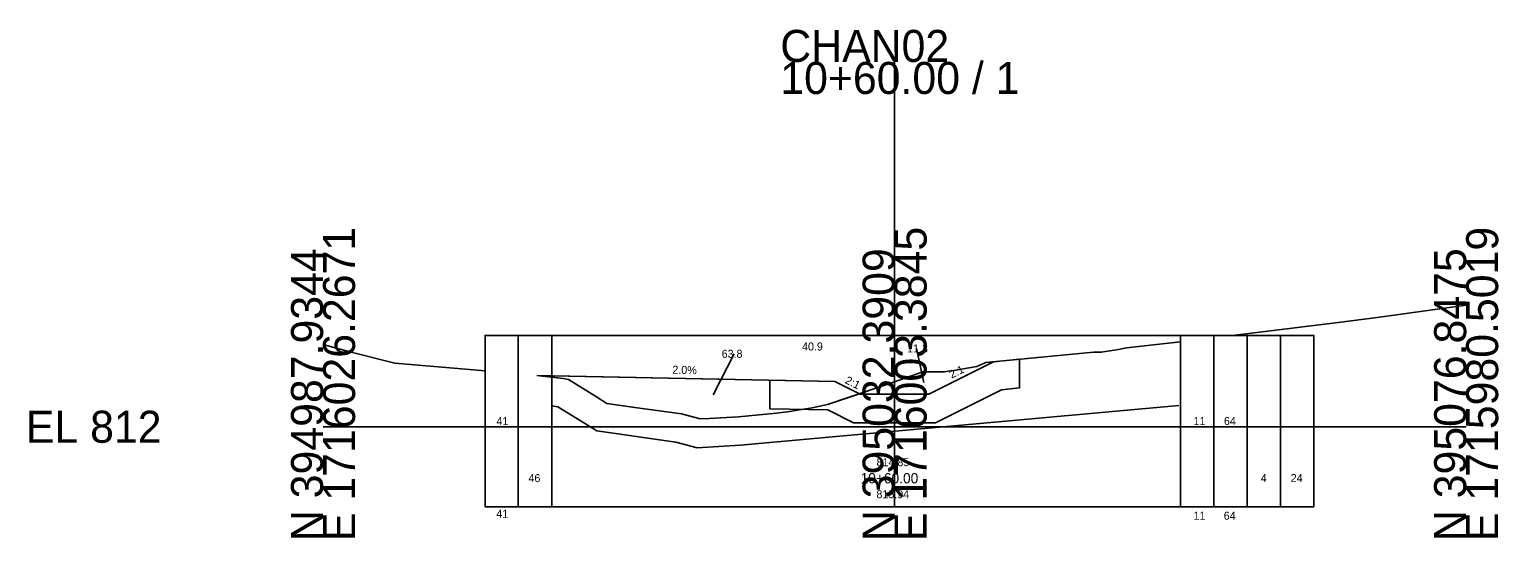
# Model space of a CAD drawing. Extents: x -26 to 103, y -10 to 16052.
# Drawn here: x -25.7 to 102.8, y 9490.3 to 9534.7 of the extents above; entities that cross this region are included whole.
import ezdxf

# ---------------------------------------------------------------- set-up
doc = ezdxf.new("R2010")
doc.units = 0
for name, color, linetype in [('GK_Cells', 7, 'Continuous'), ('SC_Scratch17', 7, 'Continuous'), ('SH_Text', 7, 'Continuous'), ('UT_X_Water', 7, 'Continuous'), ('XS_P_Annotation', 7, 'Continuous'), ('XS_P_Boundary', 7, 'Continuous'), ('XS_P_Earthwork_Shapes', 7, 'Continuous'), ('XS_P_Finished_Grade', 7, 'Continuous'), ('XS_X_Ground_Line', 7, 'Continuous')]:
    doc.layers.add(name, color=color, linetype=linetype)

msp = doc.modelspace()

# ---------------------------------------------------------------- linework, layer by layer
at = {"layer": 'GK_Cells'}
for p, q in [((50, 9500), (50, 9531.9)), ((0, 9500), (50, 9500)), ((50, 9500), (100, 9500))]:
    msp.add_line(p, q, dxfattribs=at)
at = {"layer": 'SC_Scratch17'}
msp.add_lwpolyline([(39.07, 9504.08), (44.77, 9503.97), (47, 9502.85), (53, 9502.85), (58.66, 9505.68), (60.92, 9505.9), (60.92, 9503.39), (59.36, 9503.24), (53.59, 9500.35), (46.41, 9500.35), (44.16, 9501.48), (39.07, 9501.58)], close=True, dxfattribs=at)
at = {"layer": 'UT_X_Water'}
msp.add_lwpolyline([(20, 9501.82), (20.55, 9501.75), (22.59, 9500.5), (23.94, 9499.63), (30.86, 9498.66), (32.73, 9498.16), (36.52, 9498.39), (74.85, 9501.87)], dxfattribs=at)
at = {"layer": 'XS_P_Boundary'}
for p, q in [((17.08, 9493.01), (17.08, 9507.99)), ((20, 9493.01), (20, 9507.99)), ((50, 9493.01), (50, 9507.99)), ((75, 9493.01), (75, 9507.99)), ((77.92, 9493.01), (77.92, 9507.99)), ((80.83, 9493.01), (80.83, 9507.99)), ((83.75, 9493.01), (83.75, 9507.99)), ((15.63, 9500.5), (15.63, 9500.5)), ((76.46, 9500.5), (76.46, 9500.5)), ((79.38, 9500.5), (79.38, 9500.5)), ((18.54, 9495.51), (18.54, 9495.51)), ((82.29, 9495.51), (82.29, 9495.51)), ((85.21, 9495.51), (85.21, 9495.51))]:
    msp.add_line(p, q, dxfattribs=at)
msp.add_lwpolyline([(14.17, 9493.01), (14.17, 9507.99), (86.67, 9507.99), (86.67, 9493.01)], close=True, dxfattribs=at)
at = {"layer": 'XS_P_Earthwork_Shapes'}
for p, q in [((34.12, 9502.79), (35.97, 9506.38)), ((52.56, 9503.88), (51.92, 9506.85)), ((53, 9502.85), (58.66, 9505.68)), ((58.66, 9505.68), (57.98, 9505.61)), ((44.77, 9503.97), (20, 9504.46)), ((20, 9504.46), (20, 9504.34)), ((20, 9504.34), (21.01, 9504.22)), ((46.92, 9502.89), (44.77, 9503.97)), ((47, 9502.85), (53, 9502.85))]:
    msp.add_line(p, q, dxfattribs=at)
for points in [[(18.71, 9504.49), (44.77, 9503.97), (47, 9502.85), (53, 9502.85), (58.66, 9505.68)], [(57.98, 9505.61), (57.18, 9505.26), (55.02, 9504.9), (54.68, 9504.86), (54.36, 9504.81), (52.47, 9504.79), (50, 9503.94), (46.98, 9502.91)], [(21.01, 9504.22), (21.47, 9504.12), (23.92, 9502.62), (24.83, 9502.03), (27.26, 9501.69), (31.37, 9501.12), (32.98, 9500.68), (33.78, 9500.73), (36.33, 9500.88), (39.67, 9501.19), (40.82, 9501.34), (41.49, 9501.45), (42.78, 9501.65), (44.13, 9501.94), (46.92, 9502.89)], [(46.98, 9502.91), (47, 9502.85)]]:
    msp.add_lwpolyline(points, dxfattribs=at)
at = {"layer": 'XS_P_Finished_Grade'}
for p, q in [((58.66, 9505.68), (53, 9502.85)), ((44.77, 9503.97), (18.71, 9504.49)), ((44.77, 9503.97), (47, 9502.85)), ((47, 9502.85), (53, 9502.85))]:
    msp.add_line(p, q, dxfattribs=at)
at = {"layer": 'XS_X_Ground_Line'}
for points in [[(79.55, 9507.99), (88.8, 9509.13), (92.22, 9509.55), (100, 9510.63)], [(0, 9507.2), (2.34, 9506.56), (6.27, 9505.56), (14.17, 9504.88)], [(18.71, 9504.49), (21.01, 9504.22), (21.47, 9504.12), (23.92, 9502.62), (24.83, 9502.03), (27.26, 9501.69), (31.37, 9501.12), (32.98, 9500.68), (33.78, 9500.73), (36.33, 9500.88), (39.67, 9501.19), (40.82, 9501.34), (41.49, 9501.45), (42.78, 9501.65), (44.13, 9501.94), (50, 9503.94), (52.47, 9504.79), (54.36, 9504.81), (54.68, 9504.86), (55.02, 9504.9), (57.18, 9505.26), (57.98, 9505.61), (67.4, 9506.53), (68.08, 9506.51), (69.59, 9506.77), (70.28, 9506.9), (75, 9507.44)]]:
    msp.add_lwpolyline(points, dxfattribs=at)

# ---------------------------------------------------------------- texts
at = {"layer": 'GK_Cells'}
for s, p in [('CHAN02', (40, 9531.9)), ('10+60.00 / 1', (40, 9529.1)), ('EL 812', (-26, 9498.6))]:
    msp.add_text(s, height=2.8, dxfattribs=at).set_placement(p)
for s, p in [('E 1716026.2671', (2.8, 9490)), ('E 1716003.3845', (52.8, 9490)), ('E 1715980.5019', (102.8, 9490)), ('N 394987.9344', (0, 9490)), ('N 395032.3909', (50, 9490)), ('N 395076.8475', (100, 9490))]:
    msp.add_text(s, height=2.8, rotation=90, dxfattribs=at).set_placement(p)
at = {"layer": 'SH_Text'}
for s, p in [('41', (15.17, 9500.15)), ('11', (76.15, 9500.15)), ('64', (78.81, 9500.15)), ('46', (17.97, 9495.16)), ('4', (82.03, 9495.16)), ('24', (84.65, 9495.16)), ('41', (15.16, 9492.04)), ('11', (76.15, 9491.87)), ('64', (78.79, 9491.87))]:
    msp.add_text(s, height=0.7, dxfattribs=at).set_placement(p)
at = {"layer": 'XS_P_Annotation'}
for s, rotation, p in [('2.0%', 358.8542, (30.55, 9504.64)), ('2:1', 26.5651, (54.99, 9504.2)), ('2:1', 333.4349, (45.6, 9503.84))]:
    msp.add_text(s, height=0.7, rotation=rotation, dxfattribs=at).set_placement(p)
for s, height, p in [('814.85', 0.7, (48.42, 9496.55)), ('10+60.00', 0.9, (47.02, 9495.05)), ('815.94', 0.7, (48.41, 9493.75))]:
    msp.add_text(s, height=height, dxfattribs=at).set_placement(p)
at = {"layer": 'XS_P_Earthwork_Shapes'}
for s, p in [('63.8', (34.87, 9506.03)), ('40.9', (41.9, 9506.67)), ('11.3', (51.09, 9506.5))]:
    msp.add_text(s, height=0.7, dxfattribs=at).set_placement(p)

doc.saveas('drawing.dxf')
